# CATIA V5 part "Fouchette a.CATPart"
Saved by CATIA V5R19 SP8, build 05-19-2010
Part number: Fouchette a
Bounding box of the stored display mesh (mm): x -40 to 35, y -62.897 to 62.897, z -40 to 88
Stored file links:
  F:\CFAO\Hberriche\Fouchette a.CATPart
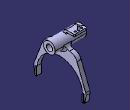
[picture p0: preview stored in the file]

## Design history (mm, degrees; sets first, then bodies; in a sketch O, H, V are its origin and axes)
Body1 (main body)
  Sketch1 on yz-plane, origin (0, 0, 0), H (0, 1, 0), V (0, 0, 1)
    line L1 (-54.7472, -20) -> (-54.7472, -40)
    point P1 (-54.7472, -20)
    point P2 (-54.7472, -40)
    point P3 (55.0096, -26.2979)
    arc A1 centre (0, -27) radius 55.1929 from (0, 28.1929) to (-54.7472, -20) ccw
    point P4 (0, -27)
    point P5 (-54.7472, -20)
    line L2 (-54.7472, -40) -> (-59.7472, -40)
    point P6 (-59.7472, -40)
    line L3 (-59.7472, -40) -> (-63.2737, -20)
    point P7 (-63.2737, -20)
    line L4 (-63.2737, -20) -> (-36.3479, 50)
    point P8 (-36.3479, 50)
    line L5 (-36.3479, 50) -> (0, 50)
    point P9 (-36.3479, 50)
    axis line L6 (0, 72.9256) -> (0, -136.9568)
    point P10 (0, 72.9256)
    point P12 (0, 50)
    point P13 (0, 28.1929)
    point P14 (0, 0)
    construction line L7 through (0, 0) direction (0, 1)
    point P17 (54.7472, -20)
    point P18 (54.7472, -40)
    point P20 (54.7472, -20)
    point P21 (59.7472, -40)
    point P22 (63.2737, -20)
    point P23 (36.3479, 50)
    point P24 (36.3479, 50)
    point P25 (0, 50)
    point P26 (0, 28.1929)
    line L8 (54.7472, -20) -> (54.7472, -40)
    arc A2 centre (0, -27) radius 55.1929 from (0, 28.1929) to (54.7472, -20) cw
    line L9 (54.7472, -40) -> (59.7472, -40)
    line L10 (59.7472, -40) -> (63.2737, -20)
    line L11 (63.2737, -20) -> (36.3479, 50)
    line L12 (36.3479, 50) -> (0, 50)
    distance P4 O = 27
    length L1 = 20
    radius A1 = 55.1929
    angle L3 L2 = 100
    length L2 = 5
    distance H L2 = 40
    distance L5 H = 50
    distance P7 H = 20
    length L4 = 75
    vertical: L1 V, L6 V
    coincidence: P4 V, P5 P1, P9 P8, P10 V, L6 P12, L6 P13, P12 P25, P13 P26, P17 P20, P23 P24
    horizontal: L2 H, L5 H
    symmetry: O P14 L6, V L7 L6, P1 P17 L6, P2 P18 L6, P5 P20 L6, P6 P21 L6, P7 P22 L6, P8 P23 L6, P9 P24 L6, P12 P25 L6, P13 P26 L6, L1 L8 L6, A1 A2 L6, L2 L9 L6, L3 L10 L6, L4 L11 L6, L5 L12 L6
  Pad1: profile Sketch1, direction (1, 0, 0), length 10
  Fillet1: radius 20, on edge [face of Pad1 from Sketch1.L4 | face of Pad1 from Sketch1.L5]; edge [face of Pad1 from Sketch1.L12 | face of Pad1 from Sketch1.L11]
  Fillet2: radius 10, on edge [face of Pad1 from Sketch1.L11 | face of Pad1 from Sketch1.L10]; edge [face of Pad1 from Sketch1.L3 | face of Pad1 from Sketch1.L4]
  Sketch2 on end face of Pad1, origin (10, 0, 0), H (0, 1, 0), V (0, 0, 1)
    circle A1 centre (0, 57.8119) radius 14
    point P1 (0, 57.8119)
    circle A2 centre (0, 57.8119) radius 7.5
    radius A2 = 7.5
    radius A1 = 14
    distance P1 H = 57.8119
    coincidence: P1 V
  Pad2: profile Sketch2, direction (1, 0, 0), length 50, mirrored extent
  Fillet3: radius 10, on edge [face of Pad2 from Sketch2.A1 | face of Pad1 from Sketch1.L12]
  Fillet4: radius 10, on edge [face of Pad1 from Sketch1.L5 | face of Pad2 from Sketch2.A1]
  Fillet5: radius 5, on edge [face of Pad2 from Sketch2.A1 | start face of Pad1]
  Fillet6: radius 5, on edge [end face of Pad1 | face of Pad2 from Sketch2.A1]
  Sketch3 on start face of Pad1, origin (0, 0, 0), H (0, -1, 0), V (0, 0, 1)
    axis line L1 (0, 18.2812) -> (0, -60.1212)
    point P1 (0, 18.2812)
    point P3 (-57.7472, -22)
    line L2 (-57.7472, -22) -> (-54.7472, -22)
    line L3 (-54.7472, -22) -> (-54.7472, -40)
    line L4 (-54.7472, -40) -> (-57.7472, -40)
    line L5 (-57.7472, -40) -> (-57.7472, -22)
    point P4 (-54.7472, -22)
    point P5 (-54.7472, -40)
    point P6 (-57.7472, -40)
    reference projected line E1 (-54.7472, -20) -> (-54.7472, -40) from edge [start face of Pad1 | face of Pad1 from Sketch1.L8]
    reference projected line E2 (-54.7472, -40) -> (-59.7472, -40) from edge [start face of Pad1 | face of Pad1 from Sketch1.L9]
    point P7 (57.7472, -22)
    point P8 (54.7472, -22)
    point P9 (54.7472, -40)
    point P10 (57.7472, -40)
    line L6 (57.7472, -22) -> (54.7472, -22)
    line L7 (54.7472, -22) -> (54.7472, -40)
    line L8 (54.7472, -40) -> (57.7472, -40)
    line L9 (57.7472, -40) -> (57.7472, -22)
    length L5 = 18
    length L2 = 3
    coincidence: P1 V, E1 L3, E2 L4
    vertical: L1 V, L3 V, L5 V
    horizontal: L2 H, L4 H
    symmetry: P3 P7 L1, P4 P8 L1, P5 P9 L1, P6 P10 L1, L2 L6 L1, L3 L7 L1, L4 L8 L1, L5 L9 L1
  Pad3: profile Sketch3, direction (-1, 0, 0), length 1.5
  Chamfer1: length 1, angle 45, on edge [start face of Pad1 | face of Pad3 from Sketch3.L5]; edge [start face of Pad1 | face of Pad3 from Sketch3.L9]
  Chamfer2: length 1, angle 45, on edge [face of Pad3 from Sketch3.L6 | start face of Pad1]; edge [face of Pad3 from Sketch3.L2 | start face of Pad1]
  Sketch4 on end face of Pad1, origin (10, 0, 0), H (0, 1, 0), V (0, 0, 1)
    point P1 (-57.7472, -22)
    line L1 (-57.7472, -22) -> (-54.7472, -22)
    line L2 (-54.7472, -22) -> (-54.7472, -40)
    line L3 (-54.7472, -40) -> (-57.7472, -40)
    line L4 (-57.7472, -40) -> (-57.7472, -22)
    point P2 (-54.7472, -22)
    point P3 (-54.7472, -40)
    point P4 (-57.7472, -40)
    reference projected line E1 (-54.7472, -40) -> (-54.7472, -20) from edge [face of Pad3 | end face of Pad1]
    reference projected line E2 (-59.7472, -40) -> (-54.7472, -40) from edge [face of Pad3 | end face of Pad1]
    axis line L5 (0, 14.1805) -> (0, -71.2709)
    point P5 (0, 14.1805)
    point P7 (57.7472, -22)
    point P8 (54.7472, -22)
    point P9 (54.7472, -40)
    point P10 (57.7472, -40)
    line L6 (57.7472, -22) -> (54.7472, -22)
    line L7 (54.7472, -22) -> (54.7472, -40)
    line L8 (54.7472, -40) -> (57.7472, -40)
    line L9 (57.7472, -40) -> (57.7472, -22)
    length L1 = 3
    length L4 = 18
    horizontal: L1 H, L3 H
    vertical: L2 V, L4 V, L5 V
    coincidence: E1 L2, E2 L3, P5 V
    symmetry: P1 P7 L5, P2 P8 L5, P3 P9 L5, P4 P10 L5, L1 L6 L5, L2 L7 L5, L3 L8 L5, L4 L9 L5
  Pad4: profile Sketch4, direction (1, 0, 0), length 1.5
  Chamfer3: length 1, angle 45, on edge [end face of Pad1 | face of Pad4 from Sketch4.L9]; edge [end face of Pad1 | face of Pad4 from Sketch4.L4]
  Chamfer4: length 1, angle 45, on edge [face of Pad4 from Sketch4.L1 | end face of Pad1]; edge [face of Pad4 from Sketch4.L6 | end face of Pad1]
  Plane1: type Offset, RefPlane xy-plane, Offset 70
  Sketch5 on Plane1, origin (0, 0, 70), H (1, 0, 0), V (0, 1, 0)
    point P1 (0, 0)
    line L1 (0, 0) -> (-25, 0)
    line L2 (-25, 0) -> (-25, 4)
    line L3 (-25, 4) -> (0, 4)
    line L4 (0, 4) -> (0, 0)
    length L2 = 4
    length L3 = 25
    coincidence: P1 H, V L4
    horizontal: L1 H, L3 H
    vertical: L2 V, L4 V
  Pad5: profile Sketch5, direction (0, 0, 1), length 5
  Sketch6 on end face of Pad5, origin (0, 0, 75), H (1, 0, 0), V (0, 1, 0)
    line L1 (0, 23) -> (0, 0)
    point P1 (0, 25)
    point P2 (0, 0)
    line L2 (0, 0) -> (-25, 0)
    line L3 (-25, 0) -> (-25, 13.4981)
    point P4 (-30, 15)
    line L4 (-2, 25) -> (-27, 25)
    point P5 (-30, 25)
    line L5 (-30, 22) -> (-30, 18.3393)
    reference projected line E1 (-25, 0) -> (0, 0) from edge [face of Pad5 from Sketch5.L1 | end face of Pad5]
    reference projected line E2 (-25, 4) -> (-25, 0) from edge [face of Pad5 from Sketch5.L2 | end face of Pad5]
    arc A1 centre (-27, 18.3393) radius 3 from (-30, 18.3393) to (-27.6117, 15.4023) ccw
    point P7 (-27.6117, 15.4023)
    arc A2 centre (-27, 13.4981) radius 2 from (-27.6117, 15.4023) to (-25, 13.4981) cw
    point P9 (-27.6117, 15.4023)
    arc A3 centre (-27, 22) radius 3 from (-27, 25) to (-30, 22) ccw
    arc A4 centre (-2, 23) radius 2 from (-2, 25) to (0, 23) cw
    distance P5 P4 = 10
    radius A1 = 3
    radius A2 = 2
    distance P1 P5 = 30
    radius A3 = 3
    distance P1 P2 = 25
    radius A4 = 2
    coincidence: P1 V, E1 L2, E2 L3, L5 P4, P7 P9, L4 P5, L5 P5, L4 P1, L1 P1
    vertical: L1 V, L3 V, L5 V
    horizontal: L2 H, L4 H
    tangency: A1 L5, A2 L3, A3 L4, A3 L5, A4 L4, A4 L1
  Pad6: profile Sketch6, direction (0, 0, 1), length 5
  Fillet7: radius 5, on edge [face of Pad6 | end face of Pad6]
  Fillet8: radius 5, on edge [face of Pad2 from Sketch2.A1 | face of Pad6]
  Fillet9: radius 2, on edge [face of Pad5 from Sketch5.L3 | start face of Pad6]
  Fillet10: radius 2, on edge [face of Pad2 from Sketch2.A1 | face of Pad5 from Sketch5.L3]
  Sketch7 on end face of Pad6, origin (0, 0, 80), H (1, 0, 0), V (0, 1, 0)
    circle A1 centre (-15, 20.2072) radius 2.5
    point P1 (-15, 20.2072)
    reference projected line E1 (0, 0) -> (0, 23) from edge [face of Pad6 | end face of Pad6]
    radius A1 = 2.5
    distance P1 E1 = 15
  Pad7: profile Sketch7, direction (0, 0, 1), length 8
  Sketch8 on end face of Pad6, origin (0, 0, 80), H (1, 0, 0), V (0, 1, 0)
    circle A1 centre (-7.5, 19.9977) radius 2.5
    point P1 (-7.5, 19.9977)
    circle A2 centre (-22.5, 19.9977) radius 2.5
    point P2 (-22.5, 19.9977)
    reference projected line E1 (0, 0) -> (0, 23) from edge [face of Pad6 | end face of Pad6]
    reference projected line E2 (-30, 22) -> (-30, 18.3393) from edge [face of Pad6 from Sketch6.L5 | end face of Pad6]
    radius A2 = 2.5
    radius A1 = 2.5
    distance P1 E1 = 7.5
    distance E2 P2 = 7.5
  Pocket1: profile Sketch8, direction (0, 0, -1), through (limit type 3)
  Sketch9 on end face of Pad2, origin (60, 0, 0), H (0, 1, 0), V (0, 0, 1)
    circle A1 centre (0, 57.8119) radius 7.5
    point P1 (0, 57.8119)
    reference projected circle E1 centre (0, 57.8119) radius 7.5 from edge [end face of Pad2 | face of Pad2 from Sketch2.A2]
    circle A2 centre (0, 57.8119) radius 14
    radius A1 = 7.5
    radius A2 = 14
    coincidence: P1 V
    concentricity: E1 A1
  Pocket2: profile Sketch9, direction (-1, 0, 0), length 25
  Plane2: type Offset, RefPlane xy-plane, Offset 57.812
